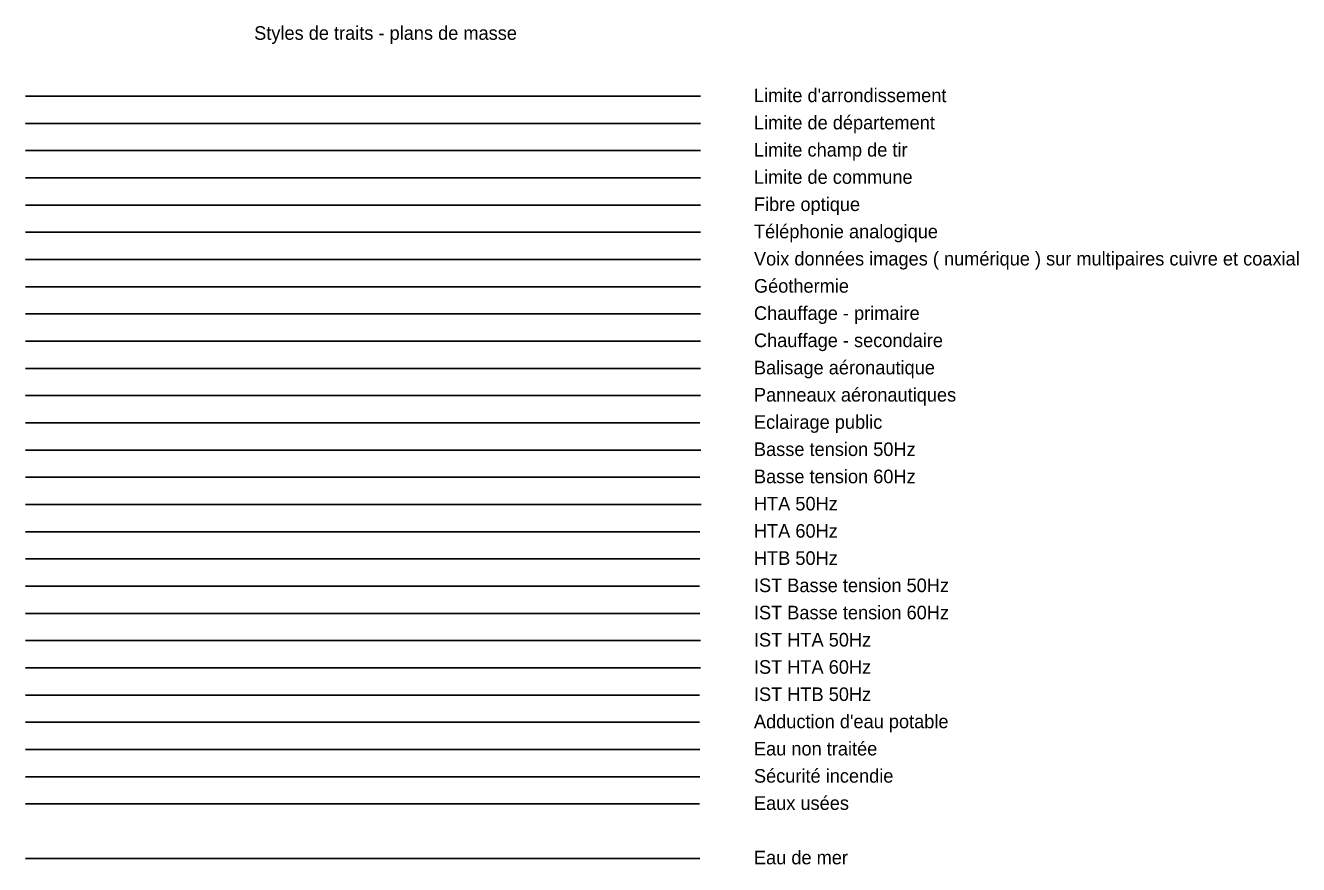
# Model space of a CAD drawing. Extents: x 3494.1 to 3554.6, y -18944.5 to -18883.7.
# Drawn here: x 3494.11 to 3540.92, y -18914.53 to -18883.71 of the extents above; entities that cross this region are included whole.
import ezdxf

# ---------------------------------------------------------------- set-up
doc = ezdxf.new("R2010")
doc.units = 0
for name, color, linetype in [('LIM_ADM ARRONDISSEMENT', 7, 'Continuous'), ('LIM_ADM DEPARTEMENT', 7, 'Continuous'), ('LIM_ADM_CHAMP TIR', 7, 'Continuous'), ('LIM_ADM_COMMUNE', 7, 'Continuous'), ('R_CF_FO_CANALISATION_CL_C', 7, 'Continuous'), ('R_CF_TEL_LIAISON_CL_C', 7, 'Continuous'), ('R_CF_VDI_LIAISON_CL_C', 7, 'Continuous'), ('R_CH_GEOTHERMIE_CANALISATION_CL_C', 7, 'Continuous'), ('R_CH_PRIM_CANALISATION_CL_C', 7, 'Continuous'), ('R_CH_SECOND_CANALISATION_CL_C', 7, 'Continuous'), ('R_ECLAIR_AERO_LIAISON_CL_C', 7, 'Continuous'), ('R_ECLAIR_PANNEAU_AERO_LIAISON_CL_C', 7, 'Continuous'), ('R_ECLAIR_PUB_LIAISON_CL_C', 7, 'Continuous'), ('R_ELEC_BT_50HZ_LIAISON_CL_C', 7, 'Continuous'), ('R_ELEC_BT_60HZ_LIAISON_CL_C', 7, 'Continuous'), ('R_ELEC_HTA_50HZ_LIAISON_CL_C', 7, 'Continuous'), ('R_ELEC_HTA_60HZ_LIAISON_CL_C', 7, 'Continuous'), ('R_ELEC_HTB_50HZ_LIAISON_CL_C', 7, 'Continuous'), ('R_ELEC_IST_BT_50HZ_LIAISON_CL_C', 7, 'Continuous'), ('R_ELEC_IST_BT_60HZ_LIAISON_CL_C', 7, 'Continuous'), ('R_ELEC_IST_HTA_50HZ_LIAISON_CL_C', 7, 'Continuous'), ('R_ELEC_IST_HTA_60HZ_LIAISON_CL_C', 7, 'Continuous'), ('R_ELEC_IST_HTB_50HZ_LIAISON_CL_C', 7, 'Continuous'), ('R_EPR_AEP_CANALISATION_CL_C', 7, 'Continuous'), ('R_EPR_EAU_NON_TRAITEE_CANALISATION_CL_C', 7, 'Continuous'), ('R_EPR_INCENDIE_CANALISATION_CL_C', 7, 'Continuous'), ('R_ES_EU_CANALISATION_CL_C', 7, 'Continuous'), ('R_ES_MER_CANALISATION_CL_C', 7, 'Continuous'), ('SO_VMC_CVC_CTA_RES-TEXTE', 7, 'Continuous')]:
    doc.layers.add(name, color=color, linetype=linetype)

msp = doc.modelspace()

# ---------------------------------------------------------------- linework, layer by layer
at = {"layer": 'LIM_ADM ARRONDISSEMENT'}
msp.add_line((3494.112, -18886.308), (3518.932, -18886.308), dxfattribs=at)
at = {"layer": 'LIM_ADM DEPARTEMENT'}
msp.add_line((3494.112, -18887.308), (3518.932, -18887.308), dxfattribs=at)
at = {"layer": 'LIM_ADM_CHAMP TIR'}
msp.add_line((3494.112, -18888.308), (3518.932, -18888.308), dxfattribs=at)
at = {"layer": 'LIM_ADM_COMMUNE'}
msp.add_line((3494.112, -18889.308), (3518.932, -18889.308), dxfattribs=at)
at = {"layer": 'R_CF_FO_CANALISATION_CL_C'}
msp.add_line((3494.112, -18890.308), (3518.932, -18890.308), dxfattribs=at)
at = {"layer": 'R_CF_TEL_LIAISON_CL_C'}
msp.add_line((3494.112, -18891.308), (3518.932, -18891.308), dxfattribs=at)
at = {"layer": 'R_CF_VDI_LIAISON_CL_C'}
msp.add_line((3494.112, -18892.308), (3518.932, -18892.308), dxfattribs=at)
at = {"layer": 'R_CH_GEOTHERMIE_CANALISATION_CL_C'}
msp.add_line((3494.112, -18893.308), (3518.932, -18893.308), dxfattribs=at)
at = {"layer": 'R_CH_PRIM_CANALISATION_CL_C'}
msp.add_line((3494.112, -18894.308), (3518.932, -18894.308), dxfattribs=at)
at = {"layer": 'R_CH_SECOND_CANALISATION_CL_C'}
msp.add_line((3494.112, -18895.308), (3518.932, -18895.308), dxfattribs=at)
at = {"layer": 'R_ECLAIR_AERO_LIAISON_CL_C'}
msp.add_line((3494.112, -18896.308), (3518.932, -18896.308), dxfattribs=at)
at = {"layer": 'R_ECLAIR_PANNEAU_AERO_LIAISON_CL_C'}
msp.add_line((3494.112, -18897.308), (3518.932, -18897.308), dxfattribs=at)
at = {"layer": 'R_ECLAIR_PUB_LIAISON_CL_C'}
msp.add_line((3494.112, -18898.308), (3518.912, -18898.308), dxfattribs=at)
at = {"layer": 'R_ELEC_BT_50HZ_LIAISON_CL_C'}
msp.add_line((3494.112, -18899.308), (3518.942, -18899.308), dxfattribs=at)
at = {"layer": 'R_ELEC_BT_60HZ_LIAISON_CL_C'}
msp.add_line((3494.112, -18900.308), (3518.905, -18900.308), dxfattribs=at)
at = {"layer": 'R_ELEC_HTA_50HZ_LIAISON_CL_C'}
msp.add_line((3494.112, -18901.308), (3518.95, -18901.308), dxfattribs=at)
at = {"layer": 'R_ELEC_HTA_60HZ_LIAISON_CL_C'}
msp.add_line((3494.112, -18902.308), (3518.905, -18902.308), dxfattribs=at)
at = {"layer": 'R_ELEC_HTB_50HZ_LIAISON_CL_C'}
msp.add_line((3494.112, -18903.304), (3518.905, -18903.304), dxfattribs=at)
at = {"layer": 'R_ELEC_IST_BT_50HZ_LIAISON_CL_C'}
msp.add_line((3494.112, -18904.308), (3518.897, -18904.308), dxfattribs=at)
at = {"layer": 'R_ELEC_IST_BT_60HZ_LIAISON_CL_C'}
msp.add_line((3494.112, -18905.308), (3518.912, -18905.308), dxfattribs=at)
at = {"layer": 'R_ELEC_IST_HTA_50HZ_LIAISON_CL_C'}
msp.add_line((3494.112, -18906.308), (3518.927, -18906.308), dxfattribs=at)
at = {"layer": 'R_ELEC_IST_HTA_60HZ_LIAISON_CL_C'}
msp.add_line((3494.112, -18907.308), (3518.927, -18907.308), dxfattribs=at)
at = {"layer": 'R_ELEC_IST_HTB_50HZ_LIAISON_CL_C'}
msp.add_line((3494.112, -18908.308), (3518.897, -18908.308), dxfattribs=at)
at = {"layer": 'R_EPR_AEP_CANALISATION_CL_C'}
msp.add_line((3494.112, -18909.308), (3518.897, -18909.308), dxfattribs=at)
at = {"layer": 'R_EPR_EAU_NON_TRAITEE_CANALISATION_CL_C'}
msp.add_line((3494.112, -18910.308), (3518.912, -18910.308), dxfattribs=at)
at = {"layer": 'R_EPR_INCENDIE_CANALISATION_CL_C'}
msp.add_line((3494.112, -18911.308), (3518.912, -18911.308), dxfattribs=at)
at = {"layer": 'R_ES_EU_CANALISATION_CL_C'}
msp.add_line((3494.112, -18912.308), (3518.897, -18912.308), dxfattribs=at)
at = {"layer": 'R_ES_MER_CANALISATION_CL_C'}
msp.add_line((3494.112, -18914.308), (3518.912, -18914.308), dxfattribs=at)

# ---------------------------------------------------------------- texts
at = {"layer": 'LIM_ADM ARRONDISSEMENT'}
msp.add_text("Limite d'arrondissement", height=0.5, dxfattribs=at).set_placement((3520.895, -18886.527))
at = {"layer": 'LIM_ADM DEPARTEMENT'}
msp.add_text('Limite de département', height=0.5, dxfattribs=at).set_placement((3520.895, -18887.527))
at = {"layer": 'LIM_ADM_CHAMP TIR'}
msp.add_text('Limite champ de tir', height=0.5, dxfattribs=at).set_placement((3520.895, -18888.527))
at = {"layer": 'LIM_ADM_COMMUNE'}
msp.add_text('Limite de commune', height=0.5, dxfattribs=at).set_placement((3520.895, -18889.527))
at = {"layer": 'R_CF_FO_CANALISATION_CL_C'}
msp.add_text('Fibre optique', height=0.5, dxfattribs=at).set_placement((3520.895, -18890.527))
at = {"layer": 'R_CF_TEL_LIAISON_CL_C'}
msp.add_text('Téléphonie analogique', height=0.5, dxfattribs=at).set_placement((3520.895, -18891.527))
at = {"layer": 'R_CF_VDI_LIAISON_CL_C'}
msp.add_text('Voix données images ( numérique ) sur multipaires cuivre et coaxial', height=0.5, dxfattribs=at).set_placement((3520.895, -18892.527))
at = {"layer": 'R_CH_GEOTHERMIE_CANALISATION_CL_C'}
msp.add_text('Géothermie', height=0.5, dxfattribs=at).set_placement((3520.895, -18893.527))
at = {"layer": 'R_CH_PRIM_CANALISATION_CL_C'}
msp.add_text('Chauffage - primaire', height=0.5, dxfattribs=at).set_placement((3520.895, -18894.527))
at = {"layer": 'R_CH_SECOND_CANALISATION_CL_C'}
msp.add_text('Chauffage - secondaire ', height=0.5, dxfattribs=at).set_placement((3520.895, -18895.527))
at = {"layer": 'R_ECLAIR_AERO_LIAISON_CL_C'}
msp.add_text('Balisage aéronautique', height=0.5, dxfattribs=at).set_placement((3520.895, -18896.527))
at = {"layer": 'R_ECLAIR_PANNEAU_AERO_LIAISON_CL_C'}
msp.add_text('Panneaux aéronautiques', height=0.5, dxfattribs=at).set_placement((3520.895, -18897.527))
at = {"layer": 'R_ECLAIR_PUB_LIAISON_CL_C'}
msp.add_text('Eclairage public', height=0.5, dxfattribs=at).set_placement((3520.895, -18898.527))
at = {"layer": 'R_ELEC_BT_50HZ_LIAISON_CL_C'}
msp.add_text('Basse tension 50Hz', height=0.5, dxfattribs=at).set_placement((3520.895, -18899.527))
at = {"layer": 'R_ELEC_BT_60HZ_LIAISON_CL_C'}
msp.add_text('Basse tension 60Hz', height=0.5, dxfattribs=at).set_placement((3520.895, -18900.527))
at = {"layer": 'R_ELEC_HTA_50HZ_LIAISON_CL_C'}
msp.add_text('HTA 50Hz', height=0.5, dxfattribs=at).set_placement((3520.895, -18901.527))
at = {"layer": 'R_ELEC_HTA_60HZ_LIAISON_CL_C'}
msp.add_text('HTA 60Hz', height=0.5, dxfattribs=at).set_placement((3520.895, -18902.527))
at = {"layer": 'R_ELEC_HTB_50HZ_LIAISON_CL_C'}
msp.add_text('HTB 50Hz', height=0.5, dxfattribs=at).set_placement((3520.895, -18903.527))
at = {"layer": 'R_ELEC_IST_BT_50HZ_LIAISON_CL_C'}
msp.add_text('IST Basse tension 50Hz', height=0.5, dxfattribs=at).set_placement((3520.895, -18904.527))
at = {"layer": 'R_ELEC_IST_BT_60HZ_LIAISON_CL_C'}
msp.add_text('IST Basse tension 60Hz', height=0.5, dxfattribs=at).set_placement((3520.895, -18905.527))
at = {"layer": 'R_ELEC_IST_HTA_50HZ_LIAISON_CL_C'}
msp.add_text('IST HTA 50Hz', height=0.5, dxfattribs=at).set_placement((3520.895, -18906.527))
at = {"layer": 'R_ELEC_IST_HTA_60HZ_LIAISON_CL_C'}
msp.add_text('IST HTA 60Hz', height=0.5, dxfattribs=at).set_placement((3520.895, -18907.527))
at = {"layer": 'R_ELEC_IST_HTB_50HZ_LIAISON_CL_C'}
msp.add_text('IST HTB 50Hz', height=0.5, dxfattribs=at).set_placement((3520.895, -18908.527))
at = {"layer": 'R_EPR_AEP_CANALISATION_CL_C'}
msp.add_text("Adduction d'eau potable ", height=0.5, dxfattribs=at).set_placement((3520.895, -18909.527))
at = {"layer": 'R_EPR_EAU_NON_TRAITEE_CANALISATION_CL_C'}
msp.add_text('Eau non traitée', height=0.5, dxfattribs=at).set_placement((3520.895, -18910.527))
at = {"layer": 'R_EPR_INCENDIE_CANALISATION_CL_C'}
msp.add_text('Sécurité incendie', height=0.5, dxfattribs=at).set_placement((3520.895, -18911.527))
at = {"layer": 'R_ES_EU_CANALISATION_CL_C'}
msp.add_text('Eaux usées', height=0.5, dxfattribs=at).set_placement((3520.895, -18912.527))
at = {"layer": 'R_ES_MER_CANALISATION_CL_C'}
msp.add_text('Eau de mer', height=0.5, dxfattribs=at).set_placement((3520.895, -18914.527))
at = {"layer": 'SO_VMC_CVC_CTA_RES-TEXTE'}
msp.add_text('Styles de traits - plans de masse', height=0.5, dxfattribs=at).set_placement((3502.52, -18884.237))

doc.saveas('drawing.dxf')
